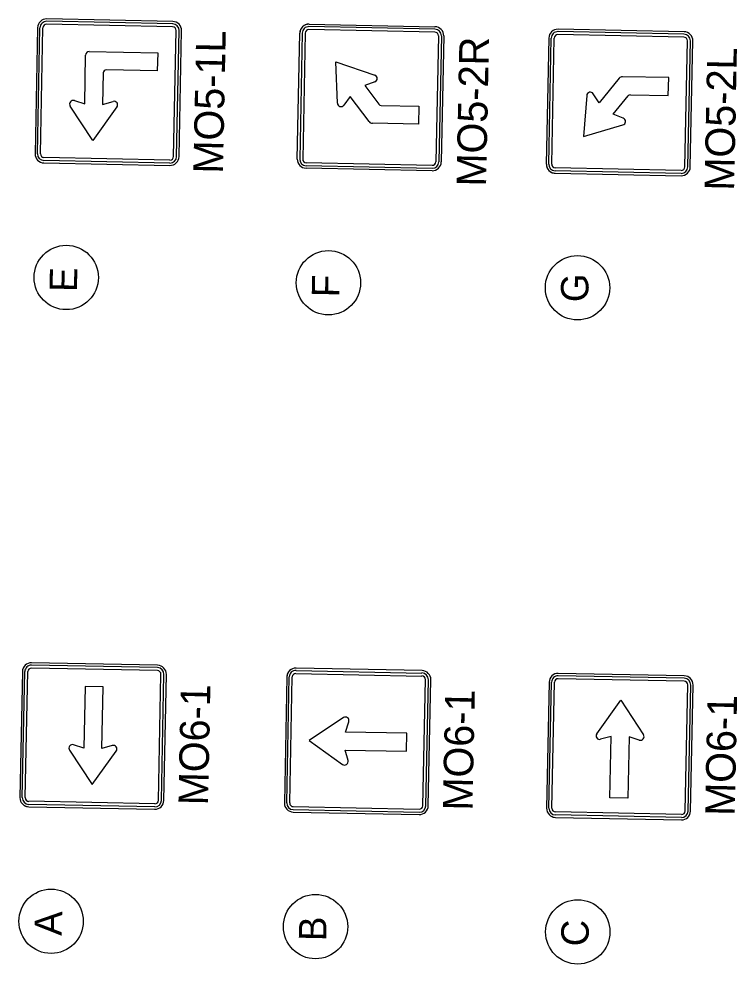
# Model space of a CAD drawing. Extents: x 335726 to 369746, y 119154 to 200788.
# Drawn here: x 352634 to 356562, y 160615 to 165783 of the extents above; entities that cross this region are included whole.
import ezdxf

# ---------------------------------------------------------------- set-up
doc = ezdxf.new("R2010")
doc.units = 0
doc.layers.add('CA-TEXT', color=7, linetype='Continuous')
doc.layers.add('P_SGN_Cell', color=7, linetype='Continuous')

msp = doc.modelspace()

# ---------------------------------------------------------------- linework, layer by layer
at = {"layer": 'CA-TEXT'}
for centre in [(352893.1, 164369.3), (354327.4, 164340.4), (355689.4, 164313), (352810.1, 160849.2), (354256.5, 160820), (355690.8, 160791.1)]:
    msp.add_circle(centre, 175.9, dxfattribs=at)
at = {"layer": 'P_SGN_Cell'}
for p, q in [((352736.4, 165734.9), (352722.6, 165046)), ((352735.7, 165045.7), (352749.6, 165734.6)), ((353475, 165739.7), (352786, 165753.6)), ((353475.3, 165756.1), (352786.4, 165770)), ((353475.6, 165769.2), (352786.6, 165783.1)), ((354909.6, 165727.2), (354220.7, 165741.1)), ((354221, 165754.2), (354909.9, 165740.3)), ((352752.1, 165045.4), (352766, 165734.3)), ((353480.4, 165030.7), (353494.3, 165719.6)), ((353496.8, 165030.4), (353510.6, 165719.3)), ((353509.9, 165030.1), (353523.8, 165719)), ((354156.9, 165017.1), (354170.7, 165706)), ((354183.9, 165705.7), (354170, 165016.8)), ((354200.3, 165705.4), (354186.4, 165016.5)), ((354909.3, 165710.8), (354220.4, 165724.7)), ((354928.6, 165690.7), (354914.7, 165001.8)), ((354945, 165690.4), (354931.1, 165001.5)), ((354958.1, 165690.1), (354944.2, 165001.2)), ((356271.3, 165683.4), (355582.4, 165697.3)), ((356271.6, 165699.8), (355582.7, 165713.7)), ((356271.9, 165712.9), (355583, 165726.8)), ((355532.7, 165678.6), (355518.9, 164989.7)), ((355532, 164989.4), (355545.9, 165678.3)), ((355548.4, 164989.1), (355562.3, 165678)), ((356276.7, 164974.4), (356290.6, 165663.3)), ((356293.1, 164974.1), (356307, 165663)), ((356306.2, 164973.8), (356320.1, 165662.7)), ((352993.9, 165317.9), (352999.3, 165585.2)), ((353019.3, 165604.5), (353393.3, 165596.9)), ((353393.3, 165596.9), (353391.3, 165498.5)), ((354376.3, 165322.5), (354367.2, 165547.8)), ((354367.2, 165547.8), (354580.8, 165475.8)), ((353095.8, 165488.1), (353092.3, 165315.9)), ((353391.3, 165498.5), (353112.5, 165504.1)), ((354581.2, 165438.6), (354525.7, 165418.4)), ((355917.5, 165458.5), (355808.7, 165324.9)), ((356188, 165461.9), (355935.8, 165467)), ((356186.1, 165363.5), (356188, 165461.9)), ((354525.7, 165418.4), (354602.1, 165316.4)), ((355808.7, 165324.9), (355775.6, 165373.9)), ((352937.6, 165336.2), (352993.9, 165317.9)), ((353092.3, 165315.9), (353149.3, 165331.9)), ((354446.9, 165359.3), (354411.8, 165311.7)), ((354550.2, 165221.5), (354446.9, 165359.3)), ((355739.7, 165364.5), (355721.5, 165139.8)), ((355885.1, 165262.8), (355965.6, 165361.6)), ((355978.6, 165367.7), (356186.1, 165363.5)), ((353039.1, 165118.4), (352915.1, 165306.6)), ((353170.6, 165301.5), (353039.1, 165118.4)), ((354614.9, 165309.8), (354822.4, 165305.6)), ((354822.4, 165305.6), (354820.4, 165207.2)), ((355939.8, 165240.3), (355885.1, 165262.8)), ((354820.4, 165207.2), (354568.1, 165212.3)), ((355721.5, 165139.8), (355937.8, 165203.2)), ((353460.3, 165011.4), (352771.4, 165025.3)), ((352770.8, 164995.8), (353459.7, 164981.9)), ((353460, 164995), (352771.1, 165008.9)), ((354894, 164953), (354205.1, 164966.9)), ((354894.3, 164966.1), (354205.4, 164980)), ((354894.6, 164982.5), (354205.7, 164996.4)), ((356256.6, 164955.1), (355567.7, 164969)), ((355567.1, 164939.5), (356256, 164925.6)), ((356256.3, 164938.7), (355567.4, 164952.6)), ((353392, 162219.6), (352703.1, 162233.4)), ((353392.3, 162236), (352703.4, 162249.8)), ((353392.6, 162249.1), (352703.7, 162263)), ((354149.8, 162220.7), (354838.7, 162206.8)), ((354839, 162220), (354150.1, 162233.8)), ((352653.5, 162214.7), (352639.6, 161525.8)), ((352652.7, 161525.6), (352666.6, 162214.5)), ((352669.1, 161525.2), (352683, 162214.2)), ((353397.4, 161510.6), (353411.3, 162199.5)), ((353413.8, 161510.2), (353427.7, 162199.2)), ((353426.9, 161510), (353440.8, 162198.9)), ((354099.8, 162185.6), (354086, 161496.7)), ((354099.1, 161496.4), (354113, 162185.4)), ((354115.5, 161496.1), (354129.4, 162185)), ((354149.5, 162204.3), (354838.4, 162190.4)), ((354843.8, 161481.4), (354857.7, 162170.4)), ((354860.2, 161481.1), (354874.1, 162170)), ((354873.3, 161480.8), (354887.2, 162169.8)), ((356272.7, 162161.6), (355583.8, 162175.4)), ((356273, 162177.9), (355584.1, 162191.8)), ((356273.3, 162191.1), (355584.4, 162204.9)), ((352996.4, 162132.4), (352989.7, 161796.2)), ((353094.8, 162130.4), (352996.4, 162132.4)), ((353088.1, 161794.2), (353094.8, 162130.4)), ((355534.2, 162156.7), (355520.3, 161467.8)), ((355533.4, 161467.6), (355547.3, 162156.5)), ((355549.8, 161467.2), (355563.7, 162156.1)), ((356278.1, 161452.6), (356292, 162141.5)), ((356294.5, 161452.2), (356308.4, 162141.1)), ((356307.6, 161452), (356321.5, 162140.9)), ((355794.5, 161874.8), (355926, 162057.9)), ((355926, 162057.9), (356050, 161869.6)), ((354409.1, 161962.6), (354220.9, 161838.6)), ((354420.4, 161883.8), (354438.7, 161940.1)), ((354756.6, 161877), (354420.4, 161883.8)), ((354754.6, 161778.6), (354756.6, 161877)), ((355872.8, 161860.3), (355815.8, 161844.3)), ((355866, 161524.1), (355872.8, 161860.3)), ((352989.7, 161796.2), (352933.4, 161814.4)), ((353145.1, 161810.2), (353088.1, 161794.2)), ((354220.9, 161838.6), (354404, 161707.1)), ((355971.2, 161858.3), (355964.5, 161522.1)), ((356027.5, 161840.1), (355971.2, 161858.3)), ((352910.9, 161784.9), (353034.9, 161596.6)), ((353034.9, 161596.6), (353166.4, 161779.7)), ((354434.4, 161728.4), (354418.4, 161785.4)), ((354418.4, 161785.4), (354754.6, 161778.6)), ((353377.3, 161491.3), (352688.4, 161505.2)), ((355964.5, 161522.1), (355866, 161524.1)), ((352687.8, 161475.6), (353376.7, 161461.7)), ((353377, 161474.9), (352688.1, 161488.7)), ((354134.2, 161446.5), (354823.1, 161432.6)), ((354134.5, 161459.6), (354823.4, 161445.8)), ((354134.8, 161476), (354823.7, 161462.1)), ((356258, 161433.3), (355569.1, 161447.1)), ((355568.5, 161417.6), (356257.4, 161403.7)), ((356257.7, 161416.9), (355568.8, 161430.7))]:
    msp.add_line(p, q, dxfattribs=at)
for centre, radius, start, end in [((352785.6, 165733.9), 49.2, 88.8462, 178.8462), ((352785.6, 165733.9), 36.1, 88.8462, 178.8462), ((352785.6, 165733.9), 19.7, 88.8462, 178.8462), ((353474.6, 165720), 19.7, 358.8462, 88.8462), ((353474.6, 165720), 36.1, 358.8462, 88.8462), ((353474.6, 165720), 49.2, 358.8462, 88.8462), ((354220, 165705), 49.2, 88.8462, 178.8462), ((354220, 165705), 36.1, 88.8462, 178.8462), ((354220, 165705), 49.2, 88.8462, 113.5578), ((354908.9, 165691.1), 49.2, 358.8462, 88.8462), ((354220, 165705), 49.2, 144.5056, 178.8462), ((354220, 165705), 19.7, 88.8462, 178.8462), ((354908.9, 165691.1), 19.7, 358.8462, 88.8462), ((354908.9, 165691.1), 36.1, 358.8462, 88.8462), ((355582, 165677.6), 49.2, 88.8462, 178.8462), ((355582, 165677.6), 36.1, 88.8462, 178.8462), ((355582, 165677.6), 19.7, 88.8462, 178.8462), ((356270.9, 165663.7), 19.7, 358.8462, 88.8462), ((356270.9, 165663.7), 36.1, 358.8462, 88.8462), ((356270.9, 165663.7), 49.2, 358.8462, 88.8462), ((353018.9, 165584.8), 19.7, 88.8462, 178.8462), ((353112.2, 165487.7), 16.4, 88.8462, 178.8462), ((354574.5, 165457.1), 19.7, 290.0436, 71.3759), ((355935.3, 165444), 23, 88.8462, 140.8466), ((355759.3, 165362.9), 19.7, 34.0436, 175.3759), ((352931.5, 165317.4), 19.7, 72.0436, 213.3759), ((353154.6, 165312.9), 19.7, 324.3166, 105.6488), ((354395.9, 165323.3), 19.7, 182.3166, 323.6488), ((355978.3, 165351.3), 16.4, 88.8462, 140.8463), ((354615.2, 165326.2), 16.4, 216.8461, 268.8462), ((354568.6, 165235.2), 23, 216.8459, 268.8462), ((355932.3, 165222), 19.7, 286.3166, 67.6488), ((352771.8, 165045), 49.2, 178.8462, 268.8462), ((352771.8, 165045), 36.1, 178.8462, 268.8462), ((352771.8, 165045), 19.7, 178.8462, 268.8462), ((353460.7, 165031.1), 49.2, 268.8462, 358.8462), ((353460.7, 165031.1), 36.1, 268.8462, 358.8462), ((353460.7, 165031.1), 19.7, 268.8462, 358.8462), ((354206.1, 165016.1), 49.2, 178.8462, 268.8462), ((354206.1, 165016.1), 36.1, 178.8462, 268.8462), ((354206.1, 165016.1), 19.7, 178.8462, 268.8462), ((354895, 165002.2), 49.2, 268.8462, 358.8462), ((354895, 165002.2), 36.1, 268.8462, 358.8462), ((354895, 165002.2), 19.7, 268.8462, 358.8462), ((355568.1, 164988.7), 49.2, 178.8462, 268.8462), ((355568.1, 164988.7), 49.2, 178.8462, 213.1868), ((355568.1, 164988.7), 36.1, 178.8462, 268.8462), ((355568.1, 164988.7), 19.7, 178.8462, 268.8462), ((356257, 164974.8), 49.2, 268.8462, 358.8462), ((356257, 164974.8), 36.1, 268.8462, 358.8462), ((356257, 164974.8), 19.7, 268.8462, 358.8462), ((355568.1, 164988.7), 49.2, 244.1347, 268.8462), ((352702.7, 162213.8), 49.2, 88.8462, 178.8462), ((352702.7, 162213.8), 36.1, 88.8462, 178.8462), ((352702.7, 162213.8), 19.7, 88.8462, 178.8462), ((353391.6, 162199.9), 36.1, 358.8462, 88.8462), ((353391.6, 162199.9), 49.2, 358.8462, 88.8462), ((354149.1, 162184.6), 49.2, 88.8462, 178.8462), ((354149.1, 162184.6), 36.1, 88.8462, 178.8462), ((353391.6, 162199.9), 19.7, 358.8462, 88.8462), ((354149.1, 162184.6), 49.2, 149.4497, 178.8462), ((354149.1, 162184.6), 19.7, 88.8462, 178.8462), ((354838, 162170.8), 19.7, 358.8462, 88.8462), ((354838, 162170.8), 36.1, 358.8462, 88.8462), ((354838, 162170.8), 49.2, 358.8462, 88.8462), ((355583.4, 162155.7), 49.2, 88.8462, 178.8462), ((355583.4, 162155.7), 36.1, 88.8462, 178.8462), ((355583.4, 162155.7), 19.7, 88.8462, 178.8462), ((356272.3, 162141.9), 36.1, 358.8462, 88.8462), ((356272.3, 162141.9), 49.2, 358.8462, 88.8462), ((356272.3, 162141.9), 19.7, 358.8462, 88.8462), ((354419.9, 161946.2), 19.7, 342.0436, 123.3759), ((355810.5, 161863.3), 19.7, 144.3166, 285.6488), ((356033.6, 161858.8), 19.7, 252.0436, 33.3759), ((352927.3, 161795.7), 19.7, 72.0436, 213.3759), ((353150.4, 161791.2), 19.7, 324.3166, 105.6488), ((354415.4, 161723.1), 19.7, 234.3166, 15.6488), ((352688.8, 161524.8), 49.2, 178.8462, 268.8462), ((352688.8, 161524.8), 36.1, 178.8462, 268.8462), ((352688.8, 161524.8), 19.7, 178.8462, 268.8462), ((353377.7, 161511), 49.2, 268.8462, 358.8462), ((353377.7, 161511), 36.1, 268.8462, 358.8462), ((353377.7, 161511), 19.7, 268.8462, 358.8462), ((352688.8, 161524.8), 49.2, 239.4497, 268.8462), ((354135.2, 161495.7), 49.2, 178.8462, 268.8462), ((354135.2, 161495.7), 36.1, 178.8462, 268.8462), ((354135.2, 161495.7), 19.7, 178.8462, 268.8462), ((354824.1, 161481.8), 49.2, 268.8462, 358.8462), ((354824.1, 161481.8), 36.1, 268.8462, 358.8462), ((354824.1, 161481.8), 19.7, 268.8462, 358.8462), ((355569.5, 161466.8), 49.2, 178.8462, 268.8462), ((355569.5, 161466.8), 36.1, 178.8462, 268.8462), ((355569.5, 161466.8), 19.7, 178.8462, 268.8462), ((356258.4, 161452.9), 49.2, 268.8462, 358.8462), ((356258.4, 161452.9), 36.1, 268.8462, 358.8462), ((356258.4, 161452.9), 19.7, 268.8462, 358.8462), ((355569.5, 161466.8), 49.2, 239.4497, 268.8462)]:
    msp.add_arc(centre, radius, start, end, dxfattribs=at)

# ---------------------------------------------------------------- texts
at = {"layer": 'CA-TEXT'}
for s, p in [('E', (352951.4, 164289.4)), ('F', (354385.7, 164260.5)), ('G', (355747.7, 164233.1)), ('A', (352868.5, 160769.3)), ('B', (354314.8, 160740.1)), ('C', (355749.2, 160711.3))]:
    msp.add_text(s, height=150, rotation=88.8468, dxfattribs=at).set_placement(p)
at = {"layer": 'P_SGN_Cell'}
for s, p in [('MO5-1L', (353750.1, 164936.1)), ('MO5-2R', (355189.2, 164865.4)), ('MO5-2L', (356545.7, 164842.9)), ('MO6-1', (353668.5, 161482.5)), ('MO6-1', (355114.8, 161453.4)), ('MO6-1', (356549.2, 161424.5))]:
    msp.add_text(s, height=162, rotation=88.8462, dxfattribs=at).set_placement(p)

doc.saveas('drawing.dxf')
